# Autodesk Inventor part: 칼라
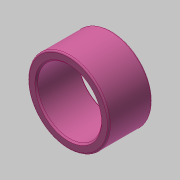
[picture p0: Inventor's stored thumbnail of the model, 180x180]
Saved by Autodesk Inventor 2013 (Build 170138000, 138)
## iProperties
Created: 2019-05
Part Number: 칼라
Material: 스테인리스강
Document SubType Name: Modeling
Designer: mduedu
Density: 1 g/cm^3
Author: mduedu
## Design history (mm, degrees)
sketch "스케치1"
  geometry: C1 r 11 at (0, 0); C2 r 14 at (0, 0); 1 further point
  constraints: 2 centre point, 2 coincident
  dimensions: "d0" = 22 diameter of C1; "d1" = 28 diameter of C2
extrude "돌출1" new body sketch "스케치1" distance "d2" = 15; taper "d3" = 0 deg
fillet "모깎기1" dims "d4" = 0.5
chamfer "모따기1" distance "d5" = 0.5; stored, may be unused: second distance "d6" = 2, angle "d7" = 45 deg
node "솔리드1"
